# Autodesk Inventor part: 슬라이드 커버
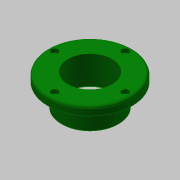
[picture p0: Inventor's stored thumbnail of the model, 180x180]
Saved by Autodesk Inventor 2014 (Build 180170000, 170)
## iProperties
Created: 2015-10
Part Number: 슬라이드 커버
Document SubType Name: Modeling
Designer: mdu
Density: 2.71 g/cm^3
Material: 알루미늄 6061
Mass: 221.924 g
Surface Area: 243.242 cm^2
Volume: 81.8907 cm^3
Appearance: Dark Green
Author: mdu
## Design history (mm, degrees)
sketch "스케치1"
  geometry: C1 r 47.5 at (0, 0); C2 r 32.5 at (0, 0); 1 further point
  constraints: 2 centre point, 2 coincident
  dimensions: "d33" = 95 diameter of C1; "d35" = 65 diameter of C2
extrude "돌출1" new body sketch "스케치1" distance "d0" = 10; taper "d1" = 0 deg
extrude "돌출2" join sketch "스케치1" distance "d2" = 26; taper "d3" = 0 deg
hole "구멍1" diameter "d6" = 50; stored, may be unused: countersink angle "d10" = 90 deg, drill point angle "d12" = 118 deg; dims "d4" = 10, "d5" = 10, "d7" = 6, "d8" = 4, "d9" = 2, "d11" = 8
sketch "스케치2" dims "d36" = 80
  geometry: 4 further points
  constraints: 2 coincident, 2 vertical alignment, 2 other
hole "구멍2" sketch "스케치2" at (0, 40) diameter "d13" = 4.5; stored, may be unused: countersink angle "d17" = 90 deg, drill point angle "d19" = 118 deg; dims "d14" = 6, "d15" = 8, "d16" = 4.4, "d18" = 8
fillet "모깎기1" dims "d23" = 3
chamfer "모따기1" distance "d24" = 1; stored, may be unused: second distance "d25" = 2, angle "d26" = 45 deg
sketch "스케치3"
  geometry: C1 r 25 at (0, 0); C2 r 30 at (0, 0); C3 r 26 at (0, 0) reference; 1 further point
  constraints: 2 centre point, 2 coincident
  dimensions: "d27" = 60 diameter of C2
extrude "돌출3" cut sketch "스케치3" distance "d28" = 3; taper "d29" = 0 deg
chamfer "모따기2" distance "d30" = 1; stored, may be unused: second distance "d31" = 2, angle "d32" = 45 deg
node "솔리드1"
pattern_circular "원형 패턴1" dims angle "d21" = 360 deg
